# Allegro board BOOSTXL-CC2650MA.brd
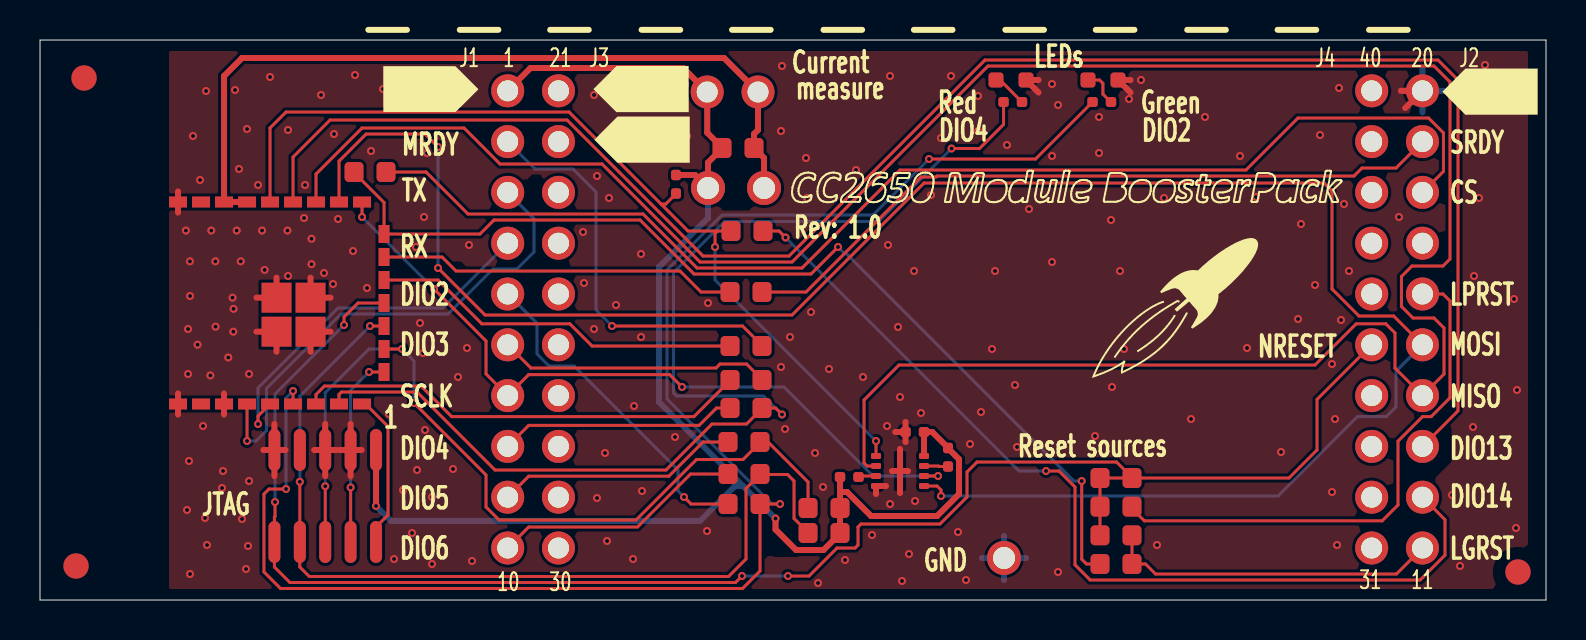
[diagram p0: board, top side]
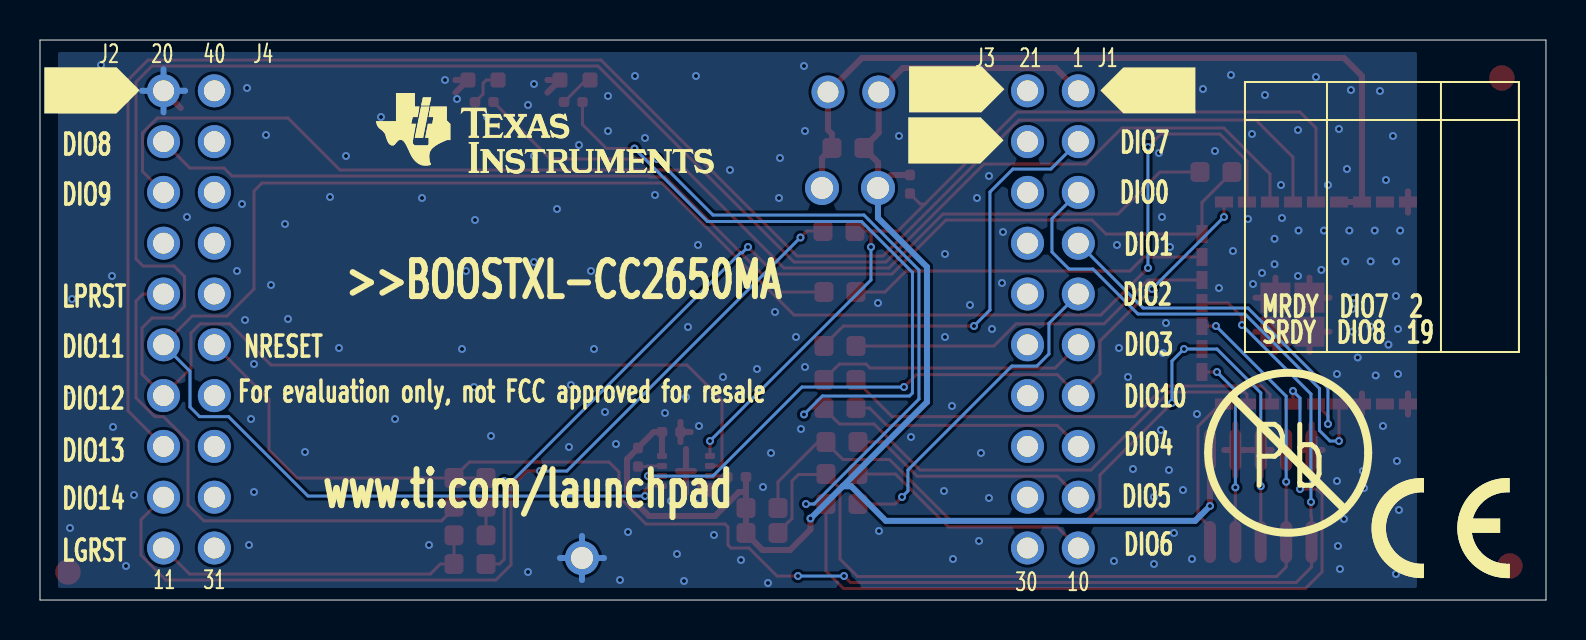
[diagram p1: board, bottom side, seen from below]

Outline 75.3 x 28 mm; copper layers: TOP, BOTTOM. Coordinates in mm from the lower left corner of the outline.
Outline path: 0,0 75.3,0 75.3,28 0,28 0,0

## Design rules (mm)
nets with their own width: min track width 0.3; nets +3.3V GND_POWER VDD_CC2650M

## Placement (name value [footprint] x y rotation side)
C1  100nF  [CAPC1005X60B2N]  44.2 8.4 180 top
CR1  LPL296-J2L2-25  [LEDC1707X65N]  53.9 26 180 top
CR2  LS L296-P2Q2-1  [LEDC1708X67N]  49.3 26 180 top
FIDU1  FIDU_1.27mm  [FID127X142]  73.9 1.4 0 top
FIDU2  FIDU_1.27mm  [FID127X142]  1.8 1.7 0 top
FIDU3  FIDU_1.27mm  [FID127X142]  2.2 26.1 0 top
J1  SSQ-110-23-L-D  [SAMTEC_SSQ11023LD_A2B]  23.39 25.46 0 bottom
J2  SSQ-110-23-L-D  [SAMTEC_SSQ11023LD_A2B]  66.59 25.46 0 bottom
LBL1  NON_COMPONENT_LABEL_8mm  [LABEL_PB-FREE_8MM_A2N]  17.1 3.15 180 bottom
LBL2  CE_label  [CE_LABEL]  6.1 1.1 180 bottom
M1  SNT-100-BK-G  [SAMTEC_SNT100BKG]  32.4 24.2 0 top
MH1  HOLE_1.1mm_PTH  [MTG110_170]  48.2 2.1 0 top
MH2  HOLE_1.1mm_PTH  [MTG110_170]  33.4 20.6 0 top
MH3  HOLE_1.1mm_PTH  [MTG110_170]  36.2 20.6 0 top
NOREF  -  []  5.9 -4.9 0 top
NOREF#2  -  []  0 22.72 0 top
NOREF#3  -  []  28.9 24.5 0 top
NOREF#4  -  []  26 20.6 0 top
NOREF#5  -  []  1.51 0 90 top
NOREF#6  -  []  68.4 23 0 top
NOREF#7  #VALUE  []  56.25 14.65 0 top
NOREF#8  -  []  48.5 85.3 0 top
NOREF#9  -  []  77.4 23.1 180 bottom
NOREF#10  -  []  22.5 24.1 180 bottom
NOREF#11  -  []  34.2 20.6 180 bottom
NOREF#12  -  []  34.3 23 180 bottom
NOREF#13  -  []  68.53 46.52 180 bottom
P2  BB02-HC021-KB1-603000  [GRADCONN_BB02HC021KB1603000_A2B]  35.9 25.4 180 top
P20  FTSH-105-01-F-DV-K  [SAMTEC_FTSH-105-01-F-DV-K-10N]  16.8 7.5 180 top
R5  180  [RESC1005X40B2N]  53.55 24.9 180 top
R6  220  [RESC1005X40B2N]  49.1 24.9 180 top
R7  0  [RESC1608X55N]  36.1 11 180 top
R8  0  [RESC1608X55N]  34.4 4.8 0 top
R9  0  [RESC1608X55N]  36.1 12.7 180 top
R10  0  [RESC1608X55N]  34.5 9.6 0 top
R11  0  [RESC1608X55N]  34.4 7.9 0 top
R12  0  [RESC1608X55N]  34.4 6.3 0 top
R13  0  [RESC1608X55N]  34.5 15.4 0 top
R16  0.1  [RESC1608X55N]  34.1 22.6 0 top
R17  0  [RESC1608X55N]  53 6.1 0 top
R18  0  [RESC1608X55N]  54.6 4.67 180 top
R19  0  [RESC1608X55N]  54.6 3.23 180 top
R20  0  [RESC1608X55N]  15.7 21.4 0 top
R21  DNM  [RESC1608X55N]  54.6 1.8 180 top
R22  DNM  [RESC1608X55N]  40 4.6 180 top
R23  DNM  [RESC1608X55N]  40 3.35 180 top
R24  0  [RESC1608X55N]  36.15 18.45 180 top
R25  10k  [RESC1005X40B2N]  31.8 21.25 270 top
R26  10k  [RESC1005X40B2N]  40 6.15 0 top
R27  10k  [RESC1005X40B2N]  45.4 7.6 270 top
U2  CC2650MODAMOH  [MODULE_CC2650MODAMOH_A2N]  6.9 9.8 0 top
U3  MX25R8035FZUIL0  [SON50P300X200X60-9B2N]  41.8 7.2 270 top
UNK#REFDES  -  []  48.4 76.65 180 bottom

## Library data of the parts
C1 = CAPACITOR: User Part Number: #PN
CR1 = LED: alternate symbols: (LEDC1707X65L,LEDC1707X65M)
CR2 = LED: alternate symbols: (LEDC1708X67L,LEDC1708X67M)
FIDU1-FIDU3 = FIDMARK
J1 J2 = CONN_HEADER_2X10_J_S_V1: User Part Number: #PN; alternate symbols: (SAMTEC_SSQ11023LD_A2C,SAMTEC_SSQ11023LD_A2A)
LBL1 = LABEL_Pb-free_V1: User Part Number: #PN
LBL2 = CE_LABEL
M1 = MECH_SHUNT_JUMPER_V1: User Part Number: #PN
MH1-MH3 = HOLE_PTH
NOREF#7 = -: User Part Number: #PN
P2 = CONN_HEADER_2_P: User Part Number: #PN; alternate symbols: (GRADCONN_BB02HC021KB1603000_A2C,GRADCONN_BB02HC021KB1603000_A2A)
P20 = CONN_HEADER_2X5: alternate symbols: (SAMTEC_FTSH-105-01-F-DV-K-10L,SAMTEC_FTSH-105-01-F-DV-K-10M)
R5 R6 R25-R27 = RESISTOR: User Part Number: #PN
R7-R13 R16-R24 = RESISTOR: alternate symbols: (RESC1608X55L,RESC1608X55M)
U2 = IC_RF_CC2650MODA_MODULE29: User Part Number: #PN
U3 = IC_FLASH_MX25R8035F_USON8: User Part Number: #PN; alternate symbols: (SON50P300X200X60-9B2L,SON50P300X200X60-9B2M)

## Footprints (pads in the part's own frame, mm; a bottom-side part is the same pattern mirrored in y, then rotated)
CAPC1005X60B2N
  custom 0.125x0.125 smd: 1(0,0) 2(0.924,0)
CE_LABEL
  oval 0.025x0.051 smd: 1(-0.15,0.1)
FID127X142
  round 1.27 smd: 1(0,0)
GRADCONN_BB02HC021KB1603000_A2B
  round 1.65 hole 1.05: 1(0,0) 2(2.54,0)
LEDC1707X65N
  custom 0.188x0.188 smd: 1(0,0) 2(1.501,0)
LEDC1708X67N
  custom 0.188x0.188 smd: 1(0,0) 2(1.501,0)
MODULE_CC2650MODAMOH_A2N
  rect 0.9x0.55 smd: 1(0,0) 2(1.15,0) 3(2.3,0) 4(3.45,0) 5(4.6,0) 6(5.75,0) 7(6.9,0) 8(8.05,0) 9(9.2,0) 17(9.2,10.1) 18(8.05,10.1) 19(6.9,10.1) 20(5.75,10.1) 21(4.6,10.1) 22(3.45,10.1) 23(2.3,10.1) 24(1.15,10.1) 25(0,10.1)
  rect 0.55x0.9 smd: 10(10.3,1.6) 11(10.3,2.75) 12(10.3,3.9) 13(10.3,5.05) 14(10.3,6.2) 15(10.3,7.35) 16(10.3,8.5)
  rect 1.5x1.5 smd: 26(4.925,3.615) 27(4.925,5.315) 28(6.625,3.615) 29(6.625,5.315)
MTG110_170
  round 1.7 hole 1.1: 1(0,0)
RESC1005X40B2N
  custom 0.125x0.125 smd: 1(0,0) 2(0.924,0)
RESC1608X55N
  custom 0.237x0.237 smd: 1(0,0) 2(1.6,0)
SAMTEC_FTSH-105-01-F-DV-K-10N
  oval 0.6x2.1 smd: 1(0,0) 2(0,4.6) 3(1.27,0) 4(1.27,4.6) 5(2.54,0) 6(2.54,4.6) 7(3.81,0) 8(3.81,4.6) 9(5.08,0) 10(5.08,4.6)
SAMTEC_SSQ11023LD_A2B
  round 1.65 hole 1.05: 1(0,0) 2(2.54,0) 3(0,2.54) 4(2.54,2.54) 5(0,5.08) 6(2.54,5.08) 7(0,7.62) 8(2.54,7.62) 9(0,10.16) 10(2.54,10.16) 11(0,12.7) 12(2.54,12.7) 13(0,15.24) 14(2.54,15.24) 15(0,17.78) 16(2.54,17.78) 17(0,20.32) 18(2.54,20.32) 19(0,22.86) 20(2.54,22.86)
SON50P300X200X60-9B2N
  custom 0.075x0.075 smd: 1(0,0) 2(0.5,0) 3(1,0) 4(1.5,0) 5(1.5,2.4) 6(1,2.4) 7(0.5,2.4) 8(0,2.4)
  rect 1.7x0.3 smd: 9(0.75,1.2)

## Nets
+3.3V: C1.1 J1.1 MH2.1 P2.2 P20.1 R16.1 R22.1 R23.1 R25.1 R26.1 R27.1 U3.8(VCC)
GND_POWER: C1.2 CR1.1(C) CR2.1(C) J2.2 MH1.1 P20.3 P20.5 P20.9 U2.1(GND#1) U2.3(GND#3) U2.25(GND#25) U2.26(EGP#26) U2.27(EGP#27) U2.28(EGP#28) U2.29(EGP#29) U3.4(GND) U3.9(EGP)
VDD_CC2650M: MH3.1 P2.1 R16.2 U2.22(VDDS#22) U2.23(VDDS#23)
CS: J2.6 R20.2
DIO0_TX: J1.5 U2.4(DIO_0)
DIO1_RX: J1.7 U2.5(DIO_1)
DIO2: R5.2 R8.2 U2.6(DIO_2)
DIO2_: J1.9 R8.1
DIO3: R7.2 U2.7(DIO_3)
DIO3_: J1.11 R7.1
DIO4: R6.2 R10.2 U2.8(DIO_4)
DIO4_: J1.15 R10.1
DIO5: P20.6 R11.2 R22.2 U2.11(DIO_5/JTAG_TDO)
DIO5_: J1.17 R11.1
DIO6: P20.8 R12.2 R23.2 U2.12(DIO_6/JTAG_TDI)
DIO6_: J1.19 R12.1
DIO7_: J1.3 R9.1
DIO7_MRDY: R9.2 U2.14(DIO_7)
DIO8_: J2.4 R13.2
DIO8_SRDY: R13.1 U2.15(DIO_8)
DIO9_CS: R20.1 R21.2 U2.16(DIO_9)
DIO10_CLK: J1.13 U2.17(DIO_10) U3.6(SCLK)
DIO11_MOSI: J2.12 U2.18(DIO_11) U3.5(SI/SIO0)
DIO12_MISO: J2.14 U2.19(DIO_12) U3.2(SO/SIO1)
DIO13: J2.16 U2.20(DIO_13)
DIO14: R24.2 R25.2 U2.21(DIO_14) U3.1(NCS)
DIO14_: J2.18 R24.1
JTAG_TCK: P20.4 U2.10(JTAG_TCKC)
JTAG_TMS: P20.2 U2.9(JTAG_TMSC)
LEGACY_RESET: J2.20 R19.1 R21.1
LP_RESET: J2.10 R18.1
NRESET: J2.11 P20.10 R17.1 R17.2 R18.2 R19.2 U2.13(NRESET)
N00827: CR2.2(A) R6.1
N00831: CR1.2(A) R5.1
N35168: R26.2 U3.3(NWP/SIO2)
N35175: R27.2 U3.7(NRST/SIO3)

Pads without a net: FIDU1 1; FIDU2 1; FIDU3 1; J1 2 4 6 8 10 12 14 16 18 20; J2 1 3 5 7 8 9 13 15 17 19; LBL2 1; P20 7; U2 2 24

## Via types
v1: diameter 0.4, hole 0.2, TOP to BOTTOM, 219 vias

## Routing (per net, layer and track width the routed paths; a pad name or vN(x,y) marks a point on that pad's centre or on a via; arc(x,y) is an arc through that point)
+3.3V: length 79.9
  TOP w0.3: 40,5.4 40.35,5.4 41.55,4.2 44.85,4.2 45.95,5.3 45.95,7.04 45.4,7.59 R27.1 45.4,7.61 44.61,8.4 C1.1 U3.8 ; 40,5.4 R22.1 R23.1 40,3.32 39.18,2.5 37.8,2.5 36.78,3.53 v1(36.78,4.07) ; 40,5.4 R26.1 ; v1(16.8,4.7) P20.1 ; R25.1 32.75,21.25 MH2.1 33.4,21.88 34.1,22.57 R16.1 34.1,22.62 33.36,23.37 P2.2 32.16,26.6 24.53,26.6 J1.1
  BOTTOM w0.3: v1(16.8,4.7) 17.54,3.96 33.01,3.96 34.74,5.69 35.17,5.69 ; v1(36.78,4.07) 35.17,5.69 ; 35.17,5.69 30.95,9.9 30.95,16.65 33.4,19.1 MH2.1
GND_POWER: length 41.8
  TOP w0.3: 43.28,7.9 C1.2 ; C1.2 43.28,8.9 ; C1.2 42.76,8.4 ; U3.9 43.4,6.45 ; U3.9 42.6,6.45 ; U3.9 43,5.35 ; U3.9 43,7.55 ; 6.9,19.37 U2.25 6.9,20.43 ; P20.3 15.53,8.8 ; P20.3 16.08,7.5 ; P20.3 14.98,7.5 ; P20.3 15.53,6.2 ; 13.53,12.41 U2.28 14.53,13.41 ; 68.05,25.46 J2.2 68.26,24.6 ; 11.83,12.41 11.83,13.41 10.83,13.41 ; P20.5 14.26,8.8 ; P20.5 14.81,7.5 ; P20.5 13.71,7.5 ; P20.5 14.26,6.2 ; 9.2,10.33 U2.3 9.2,9.27 ; 14.53,15.12 U2.29 13.53,16.12 ; 11.83,16.12 11.83,15.12 10.83,15.12 ; P20.9 11.72,8.8 ; P20.9 12.27,7.5 ; P20.9 11.72,6.2 ; P20.9 11.17,7.5 ; 41.8,5.3 U3.4 42.3,5.7 ; 6.9,10.33 U2.1 6.9,9.27 ; 49.93,26 CR2.1 49.93,25.37 ; 54.53,25.37 CR1.1 54.53,26 ; 9.63,13.41 v1(9.67,13.41)
  BOTTOM w0.3: MH1.1 49.3,2.1 ; MH1.1 47.1,2.1 ; MH1.1 48.2,3.2 ; MH1.1 48.2,1 ; J2.2 70.2,25.46 ; J2.2 69.12,24.38 ; J2.2 68.05,25.46 ; J2.2 69.12,26.54
  vias: v1(7.29,18.47) v1(7.35,4.5) v1(7.4,13.55) v1(7.4,11.3) v1(7.45,6.95) v1(7.5,16.93) v1(7.5,15.2) v1(7.5,1.3) v1(7.65,23.2) v1(7.88,12.77) v1(8,21) v1(8.15,8.7) v1(8.25,4.1) v1(8.3,25.45) v1(8.35,2.75) v1(8.52,11.23) v1(8.56,18.47) v1(8.77,16.93) v1(8.78,13.66) v1(9.1,5.6) v1(9.15,6.45) v1(9.41,12.12) v1(9.63,15.12) v1(9.68,14.56) v1(9.75,25.5) v1(9.83,18.47) v1(9.95,21.55) v1(10.04,16.93) v1(10.1,4.05) v1(10.35,23.55) v1(10.3,1.55) v1(10.45,11.3) v1(10.45,5.95) v1(10.4,2.7) v1(10.9,20.75) v1(11.1,18.47) v1(11.23,16.5) v1(11.5,26.15) v1(12.4,23.5) v1(12.37,18.47) v1(12.4,16.2) v1(13.25,20.75) v1(13.2,19.1) v1(13.58,18.06) v1(13.58,16.79) v1(14.05,25.25) v1(14.2,16.35) v1(14.7,23.3) v1(14.65,15.8) v1(14.9,19.05) v1(15.65,17.45) v1(15.75,26.25) v1(16.35,15.6) v1(16.55,22.45) v1(17.15,25.55) v1(17.45,9.3) v1(17.7,2.05) v1(18.15,5.5) v1(18.6,3.35) v1(18.8,17.65) v1(18.85,6.5) v1(19,13.85) v1(19.05,26.35) v1(19.2,25.15) v1(19.2,19.15) v1(19.15,12.35) v1(19.25,8.5) v1(19.35,22.35) v1(19.6,5.15) v1(19.6,1.8) v1(20.65,6.55) v1(20.9,11.15) v1(21.35,12.6) v1(21.45,17.75) v1(21.6,1.95) v1(27.15,18.4) v1(27.2,15.85) v1(27.7,25.25) v1(27.7,13.55) v1(27.85,21.2) v1(27.85,5.1) v1(28.25,7.35) v1(28.35,2.95) v1(28.45,20.1) v1(28.8,14.75) v1(29.7,9.7) v1(29.65,2.05) v1(30.05,17.3) v1(30.05,13.15) v1(30.1,5.45) v1(30.6,25.7) v1(31.75,8.15) v1(32.35,23.2) v1(33.35,3.45) v1(33.4,14.85) v1(37.1,26.7) v1(37.05,23.45) v1(37.05,11.65) v1(37.25,8.55) v1(37.5,13.15) v1(38.3,22.1) v1(38.35,20.1) v1(38.55,14.4) v1(38.75,7.35) v1(38.9,0.85) v1(39.15,5.65) v1(39.45,11.55) v1(40.25,2) v1(40.8,21.5) v1(41.15,11.15) v1(41.6,3.25) v1(42.35,8.7) v1(42.4,17.75) v1(42.5,26.2) v1(42.5,4.8) v1(42.9,13.65) v1(43,10.15) v1(43.1,0.95) v1(43.45,2.3) v1(43.7,16.45) v1(43.75,4.95) v1(44.05,9.35) v1(44.55,20.25) v1(45.05,23.1) v1(45.55,26.2) v1(45.9,3.4) v1(46.3,1) v1(46.5,7.8) v1(46.9,25.2) v1(46.9,23.45) v1(47.05,9.4) v1(47.6,12.55) v1(47.75,16.45) v1(48.35,22.75) v1(48.75,10.75) v1(48.85,7.65) v1(49.45,19.55) v1(50.6,25.8) v1(50.6,22.2) v1(50.6,16.9) v1(50.9,24.75) v1(50.9,1.4) v1(52.75,8.2) v1(52.95,24.15) v1(52.95,22.35) v1(53.55,19) v1(53.6,10.65) v1(54,16.45) v1(54.2,12.55) v1(54.45,25.05) v1(55.05,26) v1(55.85,2.75) v1(56.2,20.1) v1(57.55,9.05) v1(58.25,24.15) v1(60,22.2) v1(60.35,12.6) v1(60.8,20.15) v1(62.05,7.4) v1(62.9,14.05) v1(63.05,18.8) v1(63.75,15.75) v1(64,23.25) v1(64.6,11.8) v1(64.6,5.4) v1(64.75,9.05) v1(64.85,2.75) v1(64.95,25.6) v1(65.05,14) v1(65.2,19.8) v1(65.45,16.45) v1(67.95,19.15) v1(70.6,5.25) v1(71,1.7) v1(71.7,16.2) v1(71.65,8.65) v1(71.95,20.1) v1(72.25,26.75) v1(73.7,25.5) v1(73.7,15.05) v1(73.8,3.6) v1(73.85,10.5)
VDD_CC2650M: length 40.3
  TOP w0.3: MH3.1 36.2,22.1 R16.2 35.7,23.3 35.9,23.5 P2.1 34.2,27.1 10.1,27.1 9.2,26.2 U2.23 U2.22
CS: length 61.7
  TOP w0.15: R20.2 19.3,21.4 21.4,19.3 30.15,19.3 32.85,16.6 38.1,16.6 43,21.5 60.3,21.5 62.9,24.1 69.43,24.1 70.18,23.35 70.18,21.43 J2.6
DIO0_TX: length 24.9
  TOP w0.15: v1(10.35,7.95) U2.4
  BOTTOM w0.15: v1(10.35,7.95) 10.8,7.95 11.33,8.47 11.33,10.57 15.05,14.3 20.4,14.3 22.65,16.55 23.85,16.55 24.7,17.4 24.7,19.06 J1.5
DIO1_RX: length 18.5
  TOP w0.15: U2.5 10.9,9.2 v1(10.9,8.8)
  BOTTOM w0.15: v1(10.9,8.8) 10.9,10.6 14.9,14.6 20.15,14.6 J1.7
DIO2: length 79.7
  TOP w0.15: R5.2 49.78,22.05 v1(44.45,22.05) ; v1(12.3,5.55) 11.45,5.55 11.2,5.29 11.2,1.41 12.03,0.57 35.13,0.57 36,1.45 R8.2 v1(37,4.8) ; v1(12.65,10.45) U2.6
  BOTTOM w0.15: v1(12.3,5.55) 12.3,10.1 v1(12.65,10.45) ; v1(44.45,22.05) 41.65,19.25 34.1,19.25 31.35,16.5 31.35,10.05 36.6,4.8 v1(37,4.8)
DIO2_: length 16.9
  TOP w0.15: v1(32.2,5.15) 32.55,4.8 R8.1
  BOTTOM w0.15: v1(32.2,5.15) 31.9,5.45 31.9,6.5 26.7,11.7 25.45,11.7 24.85,12.3 24.85,13.83 J1.9
DIO3: length 22.8
  TOP w0.15: U2.7 13.8,10.28 14.23,10.7 19.05,10.7 20.58,9.17 32.7,9.17 34.5,10.97 R7.2
DIO3_: length 13.6
  TOP w0.15: J1.11 24.55,11.6 33.8,11.6 34,11.8 35.33,11.8 36.1,11.03 R7.1
DIO4: length 58.3
  TOP w0.15: R6.2 48.18,23.78 46.98,22.57 v1(45.58,22.57) ; U2.8 14.95,10.28 15.08,10.4 18.85,10.4 22.75,6.5 31.3,6.5 33.6,8.8 35.33,8.8 36.1,9.57 R10.2 36.78,9.6 v1(37.1,9.28)
  BOTTOM w0.15: v1(37.1,9.28) 36.18,10.2 31.83,10.2 31.68,10.35 31.68,16.38 34.23,18.93 41.93,18.93 v1(45.58,22.57)
DIO4_: length 11.9
  TOP w0.15: R10.1 33.83,9.6 32.96,8.73 24.44,8.73 J1.15
DIO5: length 42.9
  TOP w0.15: v1(18.1,12.55) U2.11 ; P20.6 v1(14.26,5.69) ; v1(18.7,9.85) 22.3,6.25 22.3,4.65 22.95,4 29.8,4 32.83,7.03 35.15,7.03 36,7.88 R11.2 36.4,7.9 38.4,5.9 R22.2
  BOTTOM w0.15: v1(18.7,9.85) 18.7,11.95 v1(18.1,12.55) 16.45,12.55 14.26,10.36 v1(14.26,5.69)
DIO5_: length 12.2
  TOP w0.15: R11.1 33.15,7.9 31.44,6.19 24.44,6.19 J1.17
DIO6: length 46.3
  TOP w0.15: 36,6.28 35.3,5.57 35.3,2.05 34.43,1.18 13.47,1.18 12.99,1.65 P20.8 v1(12.99,5.91) ; 36,6.28 37.38,6.28 37.7,5.95 37.7,4.07 38.4,3.38 R23.2 ; 36,6.28 R12.2 ; v1(16.5,13.7) U2.12
  BOTTOM w0.15: v1(12.99,5.91) 12.99,10.19 v1(16.5,13.7)
DIO6_: length 12.5
  TOP w0.15: R12.1 32.53,6.3 29.88,3.65 24.44,3.65 J1.19
DIO7_: length 20.4
  TOP w0.15: v1(28.6,13.7) 35.13,13.7 36.1,12.72 R9.1
  BOTTOM w0.15: J1.3 24.75,21.55 26.65,21.55 27.8,20.4 27.8,14.5 v1(28.6,13.7)
DIO7_MRDY: length 18.7
  TOP w0.15: R9.2 27.6,12.7 26.49,13.81 22.09,13.81 19.9,16 U2.14
DIO8_: length 36.1
  TOP w0.15: R13.2 38.3,15.4 44.05,21.15 44.8,21.15 44.85,21.2 65.7,21.2 66.1,21.6 67.81,21.6 J2.4
DIO8_SRDY: length 18
  TOP w0.15: U2.15 20.1,17.15 20.8,16.45 32,16.45 33.05,15.4 R13.1
DIO9_CS: length 50.3
  TOP w0.15: v1(52.09,5.95) 52.09,2.04 52.33,1.8 R21.2 ; v1(39.9,17.65) 38.55,16.3 32.7,16.3 30,19 22.7,19 22,18.3 U2.16 17.2,19.88 15.7,21.38 R20.1
  BOTTOM w0.15: v1(52.09,5.95) 51.69,5.95 40.27,17.37 40.19,17.37 v1(39.9,17.65)
DIO10_CLK: length 37.4
  TOP w0.15: v1(19.7,15.55) 22.3,12.95 22.3,11.3 J1.13 24.44,11.27 31.48,11.27 v1(32.1,10.65) ; U2.17 v1(16.1,19.15) ; U3.6 v1(44.9,6.2)
  BOTTOM w0.15: v1(32.1,10.65) 37.2,10.65 41.65,6.2 v1(44.9,6.2) ; v1(16.1,19.15) v1(19.7,15.55)
DIO11_MOSI: length 102.5
  TOP w0.15: v1(19.9,16.6) 22.25,14.25 37.6,14.25 44.2,20.85 64.2,20.85 64.6,20.45 64.6,20.02 64.6,15.55 65.95,14.2 67.69,14.2 J2.12 ; v1(45.05,5.2) 45.05,5.5 44.85,5.7 U3.5 ; v1(19.9,22.65) 19.25,23.3 16.31,23.3 14.95,21.94 U2.18
  BOTTOM w0.15: J2.12 67.8,11.44 67.8,9.65 67.32,9.17 65.87,9.17 61.9,5.2 v1(45.05,5.2) ; v1(19.9,16.6) v1(19.9,22.65)
DIO12_MISO: length 121.6
  TOP w0.15: U3.2 41.35,6.7 41.2,6.85 41.2,10 42.95,11.75 63.75,11.75 65.81,13.81 67.29,13.81 67.75,13.35 67.75,11.59 J2.14 70.2,11.3 70.2,13.6 69.7,14.1 68.65,14.1 68.08,14.68 68.08,16.17 68.6,16.7 70.15,16.7 70.5,17.05 70.5,25.9 69.7,26.7 47.4,26.7 37.6,16.9 33,16.9 28.1,21.8 23,21.8 21.2,23.6 16.1,23.6 13.8,21.3 U2.19
DIO13: length 87.6
  TOP w0.15: J2.16 70.9,9.46 70.9,26 69.9,27 47.25,27 37.45,17.2 33.15,17.2 26.35,24 14.5,24 12.65,22.15 U2.20
DIO14: length 45.2
  TOP w0.15: v1(41.8,7.95) U3.1 ; 31.05,19.8 32.4,18.45 33.88,18.45 ; 31.05,19.8 31.29,19.8 31.8,20.31 R25.2 ; 31.05,19.8 26.45,24.4 12.3,24.4 11.5,23.6 U2.21 ; 33.88,18.45 R24.2 ; 33.88,18.45 33.75,18.33 v1(33.75,17.65)
  BOTTOM w0.15: v1(33.75,17.65) 33.75,16 v1(41.8,7.95)
DIO14_: length 47.5
  TOP w0.15: v1(37.28,18.12) 36.95,18.45 R24.1 ; J2.18 70.25,4.01 70.25,2.24 69.01,1 52.51,1 51.75,1.76 51.75,5.65 50.95,6.45 v1(50.3,6.45)
  BOTTOM w0.15: v1(37.28,18.12) 48.95,6.45 v1(50.3,6.45)
JTAG_TCK: length 9.6
  TOP w0.15: v1(16.45,11.4) U2.10 ; P20.4 v1(15.53,5.63)
  BOTTOM w0.15: v1(16.45,11.4) 15.53,10.48 v1(15.53,5.63)
JTAG_TMS: length 7.8
  TOP w0.15: U2.9 16.28,9.8 17.4,8.68 17.4,4.25 16.8,3.65 P20.2
LEGACY_RESET: length 16.7
  TOP w0.15: R19.1 R21.1 55.28,1.8 55.78,1.3 67.83,1.3 J2.20
LP_RESET: length 27
  TOP w0.15: R18.1 54.6,4.57 55.22,3.96 67.11,3.96 67.9,4.75 67.9,7.94 69.13,9.17 69.56,9.17 70.5,10.11 70.5,14.95 70.15,15.3 J2.10
NRESET: length 84.2
  TOP w0.15: R19.2 R18.2 R17.1 R17.2 ; v1(37.4,1.2) 38.45,1.2 39.85,2.6 40.75,2.6 40.9,2.75 40.9,3.65 41.05,3.8 45,3.8 46.35,5.15 46.35,6.4 46.85,6.9 53.83,6.9 54.6,6.12 R17.2 ; R17.2 62.45,6.1 63.85,7.5 63.85,10.03 J2.11 ; v1(11.75,4.9) 11.75,4.18 11.72,4.15 P20.10 11.72,1.65 12.5,0.88 34.78,0.88 v1(35.1,1.2) ; v1(15.2,13.75) 15.2,14.15 15.9,14.85 U2.13
  BOTTOM w0.15: v1(37.4,1.2) v1(35.1,1.2) ; v1(11.75,4.9) 11.75,10.3 v1(15.2,13.75)
N00827: length 1.8
  TOP w0.15: R6.1 49.1,24.9 48.63,25.36 48.63,25.37 48,26 CR2.2
N00831: length 1.9
  TOP w0.15: CR1.2 52.98,26 53.15,25.83 53.15,25.29 53.54,24.9 R5.1
N35168: length 0.9
  TOP w0.15: U3.3 40.98,6.2 R26.2
N35175: length 1.2
  TOP w0.15: U3.7 44.93,6.7 44.95,6.68 R27.2

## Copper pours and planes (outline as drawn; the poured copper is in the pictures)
GND_POWER on TOP: 6.45,27.45 6.45,0.55 74.4,0.55 74.4,27.45 ; 42 cut-outs
GND_POWER on TOP: 46.71,0.6 46.71,6.1 49.71,6.1 49.71,0.6
GND_POWER on BOTTOM: 6.45,0.6 6.45,27.4 74.4,27.4 74.4,0.6 ; 3 cut-outs

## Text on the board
Ref Des/Silkscreen Bottom: J1 | 1 | 10 | 21 | 30 | J3 | J4 | 40 | 31 | 11 | 20 | J2 | MRDY  DIO7  2 | SRDY  DIO8  19 | DIO1 | DIO3 | DIO2 | DIO7 | DIO0 | NRESET | For evaluation only, not FCC approved for resale | DIO8 | DIO9 | LPRST | DIO11 | DIO12 | DIO13 | DIO14 | LGRST | DIO10 | DIO4 | DIO6 | DIO5 | >>BOOSTXL-CC2650MA | www.ti.com/launchpad
Ref Des/Silkscreen Top: J1 | 10 | 1 | 21 | 30 | J3 | J4 | 40 | 31 | 20 | 11 | J2 | RX | DIO2 | DIO3 | MRDY | TX | Rev: 1.0 | Red | DIO4 | LEDs | Green | NRESET | SRDY | CS | LPRST | MOSI | MISO | DIO13 | DIO14 | LGRST | JTAG | SCLK | DIO5 | DIO6 | Current | measure | GND | Reset sources
XSECTION_CHART: L1: TOP CONDUCTOR - COPPER 0.035 MM | *  DIELECTRIC - FR-4 1.53 MM | L2: BOTTOM CONDUCTOR - COPPER 0.035 MM | DESIGN CROSS SECTION CHART | ___________________________ | TOTAL THICKNESS 1.6 MM
User.7: FIGURE | SIZE | 0.2 | 1.05 | 1.1 | DRILL CHART: TOP to BOTTOM | ALL UNITS ARE IN MILLIMETERS | PLATED | QTY | 219 | 42 | 3
